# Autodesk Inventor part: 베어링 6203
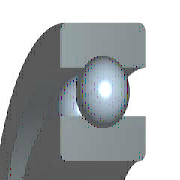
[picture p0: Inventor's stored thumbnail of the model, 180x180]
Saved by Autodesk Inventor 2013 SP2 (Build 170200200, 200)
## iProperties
IsCustomPart: 0
Created: 2009-02
Part Number: 베어링 6203
Material: 강철, 연강
Description: 깊은 그루브 볼 베어링
Document SubType Name: Modeling
Standard: KS B 2023
Standards Organization: KS
Language: ko-KR
Size Designation: 6203 - 17 x 40 x 12
Categories: <MemberInstance><Categories><Category DisplayName="샤프트 부품" InternalName="7f7aeb1f-a693-4053-b835-cee3144e0d98" Mnemonic="SHFT"><Category DisplayName="베어링" Inter
Density: 1 g/cm^3
Author: pww
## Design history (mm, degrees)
sketch "스케치" dims "d0" = 5.98 (= -0.26 x WD + 0.26 x BD)
  geometry: L1 (3.01, 14.25)-(8.99, 14.25); L2 (6, 14.25)-(6, 11.26); L3 (6, 14.25)-(6, 17.24); L4 (3.778, 12.249)-(0, 12.249); L5 (0, 8.5)-(12, 8.5); L6 (3.778, 16.251)-(0, 16.251); L7 (0, 20)-(12, 20); L8 (12, 8.5)-(12, 12.249); L9 (8.222, 12.249)-(12, 12.249); L10 (8.222, 16.251)-(12, 16.251); L11 (12, 20)-(12, 16.251); L12 (-1.4, 0)-(8.4, 0) reference; L13 (0, -0.3)-(0, 5.3) reference
  constraints: 22 end point, 4 point on line, 2 collinear, 2 perpendicular, 2 symmetric about line, 1 midpoint, 1 parallel, 14 other
  dimensions: "d9" = 17 diameter of L5 L12 (= WD); "d11" = 40 diameter of L7 L12 (= BD); "d12" = 12 distance between parallel lines of L8 L13 (= KB); "d13" = 24.498 diameter of L9 L12 (= 0.326 x BD + 0.674 x WD)
revolve "본체" stored, may be unused: angle "d6" = 90 deg
revolve "볼" stored, may be unused: angle "d7" = 90 deg
pattern_circular "IDS_ARRAYBALL[SIMPL:T]" dims angle "d3" = 360 deg
body "Solid1"
fillet "모깎기1" dims "d1" = 0.6 (= KRS)
other parameters: "WD" = 17 [user parameter; used in 5 equation terms], "BD" = 40 [user parameter; used in 5 equation terms], "KB" = 12 [user parameter; used in 1 equation term], "KRS" = 0.6 [user parameter; used in 1 equation term], "d4" = 0, "d5" = 0, "d8" = 0, "d14" = 0, "d15" = 0, "BBA" = 0 [user parameter], "BC0" = 4750000 [user parameter], "BC" = 9560000 [user parameter], "WR" = 8.5 (= 0.5 x WD) [user parameter]
